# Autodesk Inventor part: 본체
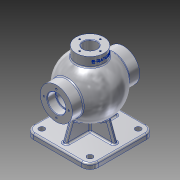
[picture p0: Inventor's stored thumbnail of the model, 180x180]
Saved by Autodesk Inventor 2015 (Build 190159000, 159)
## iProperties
Created: 2025-08
Part Number: 본체
Material: 알루미늄 6061
Document SubType Name: Modeling
Designer: USER
Density: 2.7 g/cm^3
Appearance: 알루미늄 - 평지
Mass: 1517.7 g
Surface Area: 1186.94 cm^2
Volume: 562.113 cm^3
Author: USER
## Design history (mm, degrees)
sketch "스케치1"
  geometry: L1 (-62.5, 62.5)-(62.5, 62.5); L2 (62.5, 62.5)-(62.5, -62.5); L3 (62.5, -62.5)-(-62.5, -62.5); L4 (-62.5, -62.5)-(-62.5, 62.5); L5 (-62.5, 62.5)-(62.5, -62.5); L6 (62.5, 62.5)-(-62.5, -62.5); 1 further point
  constraints: 12 end point, 2 midpoint, 2 parallel, 1 horizontal, 1 perpendicular
  dimensions: "d0" = 125 distance of L2.end L3.end; "d1" = 125 distance of L1.end L2.end
extrude "돌출1" new body sketch "스케치1" distance "d2" = 10; taper "d3" = 0 deg
fillet "모깎기1" dims "d4" = 16
sketch "스케치3"
  geometry: L1 (-4, 50.5)-(4, 50.5); L2 (4, 50.5)-(4, -50.5); L3 (4, -50.5)-(-4, -50.5); L4 (-4, -50.5)-(-4, 50.5); L5 (62.5, 46.5)-(62.5, -46.5) reference; L6 (46.5, -62.5)-(-46.5, -62.5) reference; L7 (-62.5, -46.5)-(-62.5, 46.5) reference; L8 (-46.5, 62.5)-(46.5, 62.5) reference; L9 (-50.5, 4)-(50.5, 4); L10 (50.5, 4)-(50.5, -4); L11 (50.5, -4)-(-50.5, -4); L12 (-50.5, -4)-(-50.5, 4); A1 r 16 centre (46.5, 46.5) between (62.5, 46.5) and (46.5, 62.5) reference; A2 r 16 centre (46.5, -46.5) between (46.5, -62.5) and (62.5, -46.5) reference; A3 r 16 centre (-46.5, -46.5) between (-62.5, -46.5) and (-46.5, -62.5) reference; A4 r 16 centre (-46.5, 46.5) between (-46.5, 62.5) and (-62.5, 46.5) reference; 4 further points
  constraints: 16 end point, 4 parallel, 3 midpoint, 2 horizontal, 2 perpendicular, 2 vertical alignment, 1 horizontal alignment
  dimensions: "d10" = 8 distance of L1.start L1.end; "d11" = 12 distance between parallel lines of L1 L8; "d12" = 12 distance between parallel lines of L6 L3; "d13" = 12 distance between parallel lines of L7 L12; "d14" = 8 distance of L11.end L9.start
extrude "돌출2" join sketch "스케치3" distance "d15" = 50; taper "d16" = 0 deg
sketch "스케치4"
  geometry: L1 (62.5, 10)-(62.5, 0) reference; L2 (62.5, 0)-(-62.5, 0) reference; L3 (-62.5, 0)-(-62.5, 10) reference; L4 (-62.5, 10)-(-50.5, 10) reference; L5 (-50.5, 10)-(-50.5, 60) reference; L6 (-50.5, 60)-(50.5, 60) reference; L7 (50.5, 60)-(50.5, 10) reference; L8 (50.5, 10)-(62.5, 10) reference; L9 (0, 139)-(0, 31); L10 (-4, 60)-(4, 60) reference; A1 r 54 centre (0, 85) between (0, 31) and (0, 139); 3 further points
  constraints: 2 end point, 2 midpoint, 2 point on circle, 1 centre point, 1 perpendicular, 1 vertical alignment
  dimensions: "d18" = 108 diameter of A1; "d19" = 85 distance of point (0, 0) A1.centre
revolve "회전1" sketch "스케치4" stored, may be unused: angle "d20" = 90 deg
node "작업 평면1"
sketch "스케치5"
  geometry: C1 r 31 at (0, 85); 1 further point
  constraints: 1 centre point, 1 vertical alignment
  dimensions: "d22" = 62 diameter of C1; "d23" = 85 distance of point (0, 0) C1.centre
extrude "돌출3" join sketch "스케치5" stored distance "d24" = 50; taper "d25" = 0 deg
node "작업 평면2"
sketch "스케치6"
  geometry: L1 (-4, -47.697)-(-4, -4) reference; L2 (4, -4)-(4, -47.697) reference; L3 (47.697, -4)-(4, -4) reference; L4 (4, 4)-(47.697, 4) reference; L5 (4, 44.215)-(4, 4) reference; L6 (4, 44.215)-(-4, 44.215) reference; L7 (-4, 4)-(-4, 44.215) reference; L8 (-47.697, 4)-(-4, 4) reference; L9 (-4, -4)-(-47.697, -4) reference; L10 (50.5, 4)-(50.5, -4) reference; L11 (50.5, -4)-(4, -4) reference; L12 (4, -4)-(4, -50.5) reference; L13 (4, -50.5)-(-4, -50.5) reference; L14 (-4, -50.5)-(-4, -4) reference; L15 (-4, -4)-(-50.5, -4) reference; L16 (-50.5, -4)-(-50.5, 4) reference; L17 (-50.5, 4)-(-4, 4) reference; L18 (-4, 4)-(-4, 50.5) reference; L19 (-4, 50.5)-(4, 50.5) reference; L20 (4, 50.5)-(4, 4) reference; L21 (4, 4)-(50.5, 4) reference; L22 (-62.5, 46.5)-(-62.5, -46.5) reference; L23 (-46.5, -62.5)-(46.5, -62.5) reference; L24 (62.5, -46.5)-(62.5, 46.5) reference; L25 (46.5, 62.5)-(-46.5, 62.5) reference; C1 r 27 at (0, 0); A1 r 47.864 centre (0, 0) between (-4, -47.697) and (4, -47.697) reference; A2 r 47.864 centre (0, 0) between (47.697, -4) and (47.697, 4) reference; A3 r 47.864 centre (0, 0) between (-47.697, 4) and (-47.697, -4) reference; A4 r 54 centre (0, 0) between (-31, 44.215) and (31, 44.215) reference; A5 r 16 centre (-46.5, 46.5) between (-46.5, 62.5) and (-62.5, 46.5) reference; A6 r 16 centre (-46.5, -46.5) between (-62.5, -46.5) and (-46.5, -62.5) reference; A7 r 16 centre (46.5, -46.5) between (46.5, -62.5) and (62.5, -46.5) reference; A8 r 16 centre (46.5, 46.5) between (62.5, 46.5) and (46.5, 62.5) reference; 1 further point
  constraints: 1 centre point, 1 coincident
  dimensions: "d27" = 54 diameter of C1
extrude "돌출4" join sketch "스케치6" stored distance "d28" = 50; taper "d29" = 0 deg
hole "구멍1" diameter "d34" = 30; stored, may be unused: countersink angle "d38" = 90 deg, drill point angle "d40" = 0 deg; dims "d35" = 6, "d36" = 35, "d37" = 16, "d39" = 31.5, "d43" = 10, "d44" = 10
sketch "스케치8"
  geometry: L1 (65, 54)-(50.5, 54) reference; L2 (50.5, 54)-(50.5, 10) reference; L3 (50.5, 10)-(62.5, 10) reference; L4 (62.5, 10)-(62.5, 0) reference; L5 (62.5, 0)-(-62.5, 0) reference; L6 (-62.5, 0)-(-62.5, 10) reference; L7 (-62.5, 10)-(-50.5, 10) reference; L8 (-50.5, 10)-(-50.5, 60) reference; L9 (-50.5, 60)-(-47.864, 60) reference; L10 (-27, 131.765)-(-27, 150) reference; L11 (-27, 150)-(27, 150) reference; L12 (27, 150)-(27, 131.765) reference; L13 (44.215, 116)-(65, 116) reference; L14 (65, 116)-(65, 102.5) reference; L15 (49, 100)-(33.5, 100) reference; L16 (33.5, 100)-(33.5, 70) reference; L17 (33.5, 70)-(49, 70) reference; L18 (65, 67.5)-(65, 54) reference; L19 (0, 129)-(0, 41); L20 (65, 102.5)-(49, 102.5) reference; L21 (49, 102.5)-(49, 100) reference; L22 (49, 70)-(49, 67.5) reference; L23 (49, 67.5)-(65, 67.5) reference; A1 r 54 centre (0, 85) between (-27, 131.765) and (-47.864, 60) reference; A2 r 54 centre (0, 85) between (44.215, 116) and (27, 131.765) reference; A3 r 44 centre (0, 85) between (0, 129) and (0, 41); 3 further points
  constraints: 2 end point, 2 midpoint, 2 point on circle, 1 centre point, 1 coincident, 1 vertical, 1 vertical alignment
  dimensions: "d41" = 88 diameter of A3
revolve "회전3" sketch "스케치8" stored, may be unused: angle "d42" = 90 deg
hole "구멍2" diameter "d47" = 26; stored, may be unused: countersink angle "d51" = 90 deg, drill point angle "d53" = 0 deg; dims "d45" = 10, "d46" = 10, "d48" = 6, "d49" = 35, "d50" = 16, "d52" = 26
feature "면 기울기3" dims angle "d56" = 20 deg
hole "구멍3" diameter "d59" = 11; stored, may be unused: countersink angle "d63" = 90 deg, drill point angle "d65" = 0 deg; dims "d57" = 10, "d58" = 10, "d60" = 6, "d61" = 35, "d62" = 16, "d64" = 11
sketch "스케치9"
  geometry: L1 (0, 0)-(0, 85); L2 (0, 0)-(-24, 0); C1 r 31 at (0, 0) reference
  constraints: 4 end point, 1 horizontal, 1 vertical
  dimensions: "d72" = 24 distance of L1.start L2.end
hole "구멍4" sketch "스케치9" at (-24, 0) diameter "d73" = 3.242; stored, may be unused: countersink angle "d77" = 90 deg, drill point angle "d79" = 118 deg; dims "d74" = 12, "d75" = 35, "d76" = 16, "d78" = 15
sketch "스케치10"
  geometry: 2 further points
  constraints: 1 horizontal alignment
  dimensions: "d83" = 20 distance of point (0, 0) point (20, 0)
hole "구멍5" sketch "스케치10" at (20, 0) diameter "d84" = 3.242; stored, may be unused: countersink angle "d88" = 90 deg, drill point angle "d90" = 118 deg; dims "d85" = 9, "d86" = 35, "d87" = 16, "d89" = 11
node "작업 평면3"
sketch "스케치12"
  geometry: C1 r 31 at (0, 85); 1 further point
  constraints: 1 centre point, 1 vertical alignment
  dimensions: "d95" = 62 diameter of C1; "d96" = 85 distance of point (0, 0) C1.centre
extrude "돌출5" join sketch "스케치12" stored distance "d97" = 50; taper "d98" = 0 deg
sketch "스케치13"
  geometry: L1 (-27, 150)-(27, 150) reference; L2 (-27, 131.765)-(27, 131.765) reference; L3 (-27, 150)-(27, 150) reference; L4 (-27, 150)-(-27, 131.765) reference; L5 (-27, 131.765)-(27, 131.765) reference; L6 (27, 150)-(27, 131.765) reference; 3 further points
  constraints: 1 midpoint, 1 vertical alignment, 1 other
  dimensions: "d99" = 9 distance from line of L1 point (0, 141)
feature "엠보싱1" sketch "스케치13" dims "d0" = 125, "d1" = 125, "d12" = 12, "d100" = 0.5, "d101" = 0
chamfer "모따기2" distance "d105" = 1; stored, may be unused: second distance "d106" = 2, angle "d107" = 45 deg
fillet "모깎기2" dims "d114" = 3
fillet "모깎기3" dims "d115" = 3
fillet "모깎기4" dims "d116" = 3
chamfer "모따기5" distance "d117" = 1; stored, may be unused: second distance "d118" = 2, angle "d119" = 45 deg
fillet "모깎기5" dims "d120" = 0.6
fillet "모깎기6" dims "d121" = 3
node "솔리드1"
pattern_linear "직사각형 패턴1" dims "d68" = 93, "d71" = 93
pattern_circular "원형 패턴1" dims angle "d81" = 360 deg
pattern_circular "원형 패턴2" dims angle "d92" = 360 deg
mirror "대칭2"
node "투영된 루프1"
node "투영된 루프2"
node "투영된 루프3"
node "절단 모서리 투영2"
node "절단 모서리 투영3"
node "절단 모서리 투영5"
other parameters: "d21" = 65, "d94" = -65
